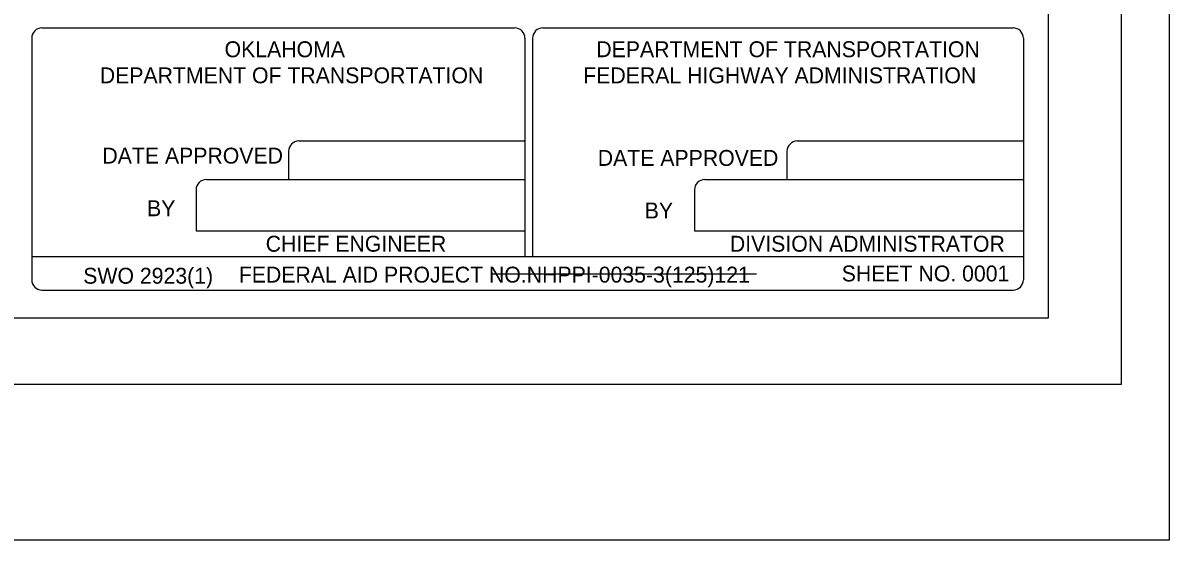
# Model space of a CAD drawing. Extents: x 2121385 to 2181200, y 132498 to 161273.
# Drawn here: x 2158702 to 2167361, y 132498 to 136404 of the extents above; entities that cross this region are included whole.
import ezdxf

# ---------------------------------------------------------------- set-up
doc = ezdxf.new("R2010")
doc.units = 0
for name, color, linetype in [('SHT_Plot_Shape_Full', 7, 'Continuous'), ('SHT_Plot_Shape_Half', 7, 'Continuous'), ('SHT_Sheet_Border', 7, 'Continuous'), ('SHT_Standard_Sheet_Lines', 7, 'Continuous'), ('SHT_Standard_Sheet_Txt', 7, 'Continuous'), ('TOPO_Concrete', 7, 'Continuous')]:
    doc.layers.add(name, color=color, linetype=linetype)

msp = doc.modelspace()

# ---------------------------------------------------------------- linework, layer by layer
at = {"layer": 'SHT_Plot_Shape_Full'}
msp.add_lwpolyline([(2131361.1, 156498.4), (2167361.1, 156498.4), (2167361.1, 132498.4), (2131361.1, 132498.4)], close=True, dxfattribs=at)
at = {"layer": 'SHT_Plot_Shape_Half'}
msp.add_lwpolyline([(2132998.6, 155673.4), (2166998.6, 155673.4), (2166998.6, 133673.4), (2132998.6, 133673.4)], close=True, dxfattribs=at)
at = {"layer": 'SHT_Sheet_Border'}
msp.add_lwpolyline([(2166448.6, 134173.4), (2134948.6, 134173.4), (2134948.6, 155173.4), (2166448.6, 155173.4)], close=True, dxfattribs=at)
at = {"layer": 'SHT_Standard_Sheet_Lines'}
for p, q in [((2158845.7, 136366.2), (2162417, 136366.2)), ((2162630.5, 136366.2), (2166182.5, 136366.2)), ((2158768.1, 136288.5), (2158768.1, 134464.1)), ((2162494.7, 136288.5), (2162494.7, 134638.7)), ((2162552.9, 136288.5), (2162552.9, 134638.7)), ((2166260.1, 136288.5), (2166260.1, 134464.1)), ((2160709, 135434.5), (2160709, 135221)), ((2160786.6, 135512.2), (2162494.7, 135512.2)), ((2164474.4, 135434.5), (2164474.4, 135221)), ((2164552.1, 135512.2), (2166260.1, 135512.2)), ((2160087.9, 135221), (2162494.7, 135221)), ((2163853.3, 135221), (2166260.1, 135221)), ((2160010.3, 135143.4), (2160010.3, 134832.8)), ((2163775.7, 135143.4), (2163775.7, 134832.8)), ((2160010.3, 134832.8), (2162494.7, 134832.8)), ((2163775.7, 134832.8), (2166260.1, 134832.8)), ((2158768.1, 134638.7), (2166260.1, 134638.7)), ((2158845.7, 134386.4), (2166182.5, 134386.4))]:
    msp.add_line(p, q, dxfattribs=at)
for centre, start, end in [((2158845.7, 136288.5), 90, 180), ((2162417, 136288.5), 0, 90), ((2162630.5, 136288.5), 90, 180), ((2166182.5, 136288.5), 0, 90), ((2160786.6, 135434.5), 90, 180), ((2164552.1, 135434.5), 90, 180), ((2160087.9, 135143.4), 90, 180), ((2163853.3, 135143.4), 90, 180), ((2158845.7, 134464.1), 180, 270), ((2166182.5, 134464.1), 270, 0)]:
    msp.add_arc(centre, 77.6, start, end, dxfattribs=at)
at = {"layer": 'TOPO_Concrete'}
msp.add_line((2164243.8, 134506.1), (2162247.9, 134506.1), dxfattribs=at)

# ---------------------------------------------------------------- texts
at = {"layer": 'SHT_Standard_Sheet_Txt'}
for s, p in [('OKLAHOMA', (2160225.4, 136145)), ('DEPARTMENT OF TRANSPORTATION', (2163033.9, 136145)), ('DEPARTMENT OF TRANSPORTATION', (2159282.6, 135947.8)), ('FEDERAL HIGHWAY ADMINISTRATION', (2162935.3, 135947.8)), ('DATE APPROVED', (2159302.3, 135341.5)), ('DATE APPROVED', (2163044.9, 135324.2)), ('BY', (2159639.9, 134944)), ('BY', (2163399.8, 134926.8)), ('CHIEF ENGINEER', (2160536.1, 134676.2)), ('DIVISION ADMINISTRATOR', (2164042.9, 134676.2)), ('FEDERAL AID PROJECT NO.NHPPI-0035-3(125)121', (2160332.8, 134442.9)), ('SHEET NO. 0001', (2164887.9, 134451.6)), ('SWO 2923(1)', (2159157.6, 134434.3))]:
    msp.add_text(s, height=120, dxfattribs=at).set_placement(p)

doc.saveas('drawing.dxf')
